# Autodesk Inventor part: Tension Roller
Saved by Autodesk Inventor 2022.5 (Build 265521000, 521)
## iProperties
Created: 2025-01
Part Number: Tension Roller
Material: Generic
Document SubType Name: Modeling
Designer: AdminForWorker
Density: 1 g/cm^3
Appearance: Default
Title: Tension Roller v9
Author: AdminForWorker
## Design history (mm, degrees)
feature "Body1"
body "Solid1"
